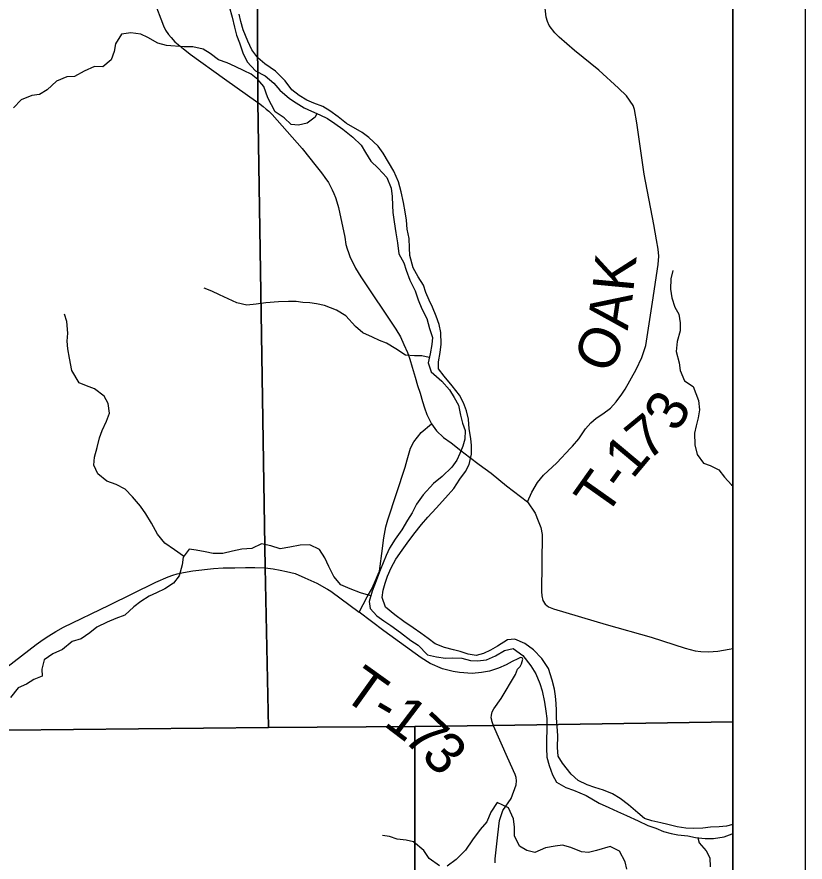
# Model space of a CAD drawing. Extents: x 0 to 34, y 0 to 22.
# Drawn here: x 7.911 to 9, y 15.737 to 16.905 of the extents above; entities that cross this region are included whole.
import ezdxf

# ---------------------------------------------------------------- set-up
doc = ezdxf.new("R2010")
doc.units = 0
for name, color, linetype in [('Default', 7, 'Continuous'), ('GM_X_County_Road', 7, 'Continuous'), ('GM_X_Minor_River', 7, 'Continuous'), ('GM_X_Township_Road', 7, 'Continuous'), ('GM_X_Township_Road_Text', 7, 'Continuous'), ('SH_Cut_Line', 7, 'Continuous'), ('SH_Data', 7, 'Continuous')]:
    doc.layers.add(name, color=color, linetype=linetype)

msp = doc.modelspace()

# ---------------------------------------------------------------- linework, layer by layer
at = {"layer": 'Default'}
for points in [[(8.9, 15.9304), (8.9, 20.9), (8.1749, 20.9), (8.1859, 20.3892), (8.1995, 19.7718), (8.2061, 19.4737), (8.2069, 19.4369), (8.2195, 18.875), (8.2216, 18.8361), (8.2229, 18.8136), (8.2232, 18.7798), (8.2237, 18.7271), (8.2254, 18.6464), (8.2283, 18.4271), (8.2338, 18.0126), (8.2361, 17.5877), (8.2392, 17.3521), (8.2417, 17.2403), (8.2434, 16.7876), (8.2536, 16.1438), (8.2582, 15.9227), (8.4608, 15.9241), (8.569, 15.9256)], [(8.4439, 14.1), (8.9, 14.1), (8.9, 15.9304), (8.569, 15.9256), (8.4608, 15.9241), (8.4608, 15.4787), (8.4328, 14.5554), (8.4328, 14.555), (8.4391, 14.4529)]]:
    msp.add_lwpolyline(points, close=True, dxfattribs=at)
for points in [[(6.5781, 15.8955), (6.9232, 15.9027), (7.0184, 15.9049), (7.3026, 15.9113), (7.5392, 15.9156), (8.2582, 15.9227), (8.2536, 16.1438), (8.2434, 16.7876), (8.2417, 17.2403), (8.2392, 17.3521), (8.2361, 17.5877), (8.2338, 18.0126), (8.2283, 18.4271), (8.2254, 18.6464), (8.2237, 18.7271), (8.2232, 18.7798), (8.2229, 18.8136), (8.2216, 18.8361), (8.2195, 18.875), (8.2069, 19.4369), (8.2061, 19.4737), (8.1995, 19.7718), (8.1859, 20.3892)], [(8.4608, 15.4787), (8.4608, 15.9241), (8.2582, 15.9227), (7.5392, 15.9156), (7.3026, 15.9113), (7.0184, 15.9049), (6.9232, 15.9027), (6.5781, 15.8955), (6.4918, 15.8937), (6.4353, 15.8916), (6.4145, 15.8911), (6.2639, 15.8885), (6.1922, 15.8873), (6.1703, 15.8865), (6.065, 15.8836), (5.9591, 15.8823), (5.7768, 15.8771), (5.0185, 15.8642), (4.6273, 15.8569), (4.3446, 15.8524)]]:
    msp.add_lwpolyline(points, dxfattribs=at)
at = {"layer": 'GM_X_County_Road'}
for points in [[(8.1, 16.9277), (8.113, 16.8928), (8.116, 16.8867), (8.12, 16.881), (8.1236, 16.8767), (8.1287, 16.8707), (8.1379, 16.8633), (8.1501, 16.8538), (8.1977, 16.8195), (8.2436, 16.787), (8.2445, 16.7863)], [(8.2445, 16.7863), (8.2512, 16.7811), (8.2552, 16.7777), (8.2586, 16.775), (8.2636, 16.7704), (8.3048, 16.7232), (8.3242, 16.6989), (8.3298, 16.6918), (8.3328, 16.6878), (8.3362, 16.6829), (8.3411, 16.6763), (8.3463, 16.6663), (8.3488, 16.6608), (8.3509, 16.6555), (8.3527, 16.6496), (8.3549, 16.6415), (8.3637, 16.6005), (8.3654, 16.5906), (8.3669, 16.5843), (8.3688, 16.5794), (8.3713, 16.5725), (8.3752, 16.5646), (8.3785, 16.5579), (8.3858, 16.5459), (8.4344, 16.4733), (8.4406, 16.4627), (8.4455, 16.4521), (8.4503, 16.4413), (8.4536, 16.4318), (8.457, 16.4208), (8.4612, 16.4072), (8.4643, 16.3954), (8.4681, 16.3849), (8.4712, 16.3736), (8.474, 16.3646), (8.4773, 16.3554), (8.4838, 16.3427)], [(8.3838, 16.0822), (8.3946, 16.1032), (8.4005, 16.1136), (8.405, 16.1227), (8.4099, 16.1346), (8.4116, 16.1387), (8.4125, 16.1456), (8.4152, 16.1633), (8.4179, 16.1851), (8.4207, 16.2), (8.4233, 16.2099), (8.4472, 16.2826), (8.4501, 16.2926), (8.4528, 16.3024), (8.4547, 16.3088), (8.4594, 16.3176), (8.4641, 16.3242), (8.4694, 16.3304), (8.4838, 16.3427)], [(8.4838, 16.3427), (8.4904, 16.3331), (8.5004, 16.3239), (8.5107, 16.3161), (8.5243, 16.3057), (8.5361, 16.2963), (8.5496, 16.2864), (8.5662, 16.2742), (8.5871, 16.2568), (8.6161, 16.2346)], [(8.6161, 16.2346), (8.6267, 16.2192), (8.6311, 16.2087), (8.6347, 16.1995), (8.6367, 16.1894), (8.6358, 16.1108), (8.636, 16.1048), (8.6377, 16.0984), (8.6406, 16.0933), (8.6455, 16.0894), (8.6522, 16.0869), (8.725, 16.0654), (8.7874, 16.0475), (8.8342, 16.0323), (8.8482, 16.0288), (8.856, 16.0277), (8.8666, 16.0272), (8.8795, 16.0283), (8.895, 16.0309), (8.9, 16.032)], [(7.8455, 15.9669), (7.9373, 16.0373), (7.9469, 16.0446), (7.9549, 16.0493), (7.9646, 16.0555), (7.9748, 16.0614), (8.0382, 16.092), (8.1027, 16.1239), (8.1197, 16.131), (8.1263, 16.1333), (8.1322, 16.1353), (8.1384, 16.1367), (8.146, 16.138), (8.1536, 16.1392), (8.1821, 16.1424), (8.1956, 16.1434), (8.212, 16.1436), (8.2267, 16.1439), (8.2393, 16.1438), (8.2538, 16.1433), (8.2648, 16.1423), (8.2743, 16.1404), (8.2834, 16.1385), (8.295, 16.1355), (8.3087, 16.1299), (8.3253, 16.1224), (8.3389, 16.1145), (8.3399, 16.114)], [(8.3399, 16.114), (8.3447, 16.1112), (8.3838, 16.0822)]]:
    msp.add_lwpolyline(points, dxfattribs=at)
at = {"layer": 'GM_X_Minor_River'}
for points in [[(8.2038, 16.9193), (8.2081, 16.9049), (8.2113, 16.8909), (8.214, 16.8799), (8.2183, 16.8693), (8.2229, 16.8557), (8.2287, 16.8429), (8.2402, 16.8308)], [(8.2438, 16.8487), (8.2354, 16.8596), (8.2296, 16.8714), (8.2234, 16.8872), (8.2203, 16.8986), (8.2179, 16.9088)], [(8.3252, 16.7716), (8.323, 16.7667), (8.3117, 16.7582), (8.2996, 16.7554), (8.2897, 16.7565), (8.2798, 16.7655), (8.2676, 16.7737), (8.2572, 16.7934), (8.2518, 16.8089), (8.2437, 16.8187), (8.2342, 16.8262), (8.2247, 16.8307), (8.2125, 16.8366), (8.2011, 16.8415), (8.1893, 16.8459), (8.1778, 16.8545), (8.1679, 16.8605), (8.1539, 16.8638), (8.1417, 16.8637), (8.1175, 16.8657), (8.1053, 16.8687), (8.0916, 16.8765), (8.0817, 16.8813), (8.068, 16.8831), (8.0552, 16.8815), (8.0469, 16.8677), (8.0448, 16.8574), (8.0407, 16.846), (8.0294, 16.836), (8.018, 16.8367), (8.0037, 16.8301), (7.9901, 16.8227), (7.9795, 16.8223), (7.9655, 16.8161), (7.9523, 16.8042), (7.9418, 16.798), (7.9312, 16.7964), (7.9165, 16.7905), (7.9059, 16.7794)], [(8.6864, 15.8496), (8.6769, 15.8582), (8.6646, 15.8733), (8.6588, 15.8831), (8.6576, 15.8953), (8.6582, 15.9112), (8.6574, 15.9245), (8.6565, 15.9363), (8.6564, 15.9465), (8.6559, 15.956), (8.6551, 15.9659), (8.6535, 15.9757), (8.6504, 15.9882), (8.6453, 16.0045), (8.6361, 16.0181), (8.6246, 16.0301), (8.6128, 16.0391), (8.5987, 16.0447), (8.5889, 16.0442), (8.5749, 16.0354), (8.5651, 16.0296), (8.5553, 16.0253), (8.5454, 16.0225), (8.5344, 16.024), (8.5234, 16.028), (8.5139, 16.0302), (8.5014, 16.0335), (8.4885, 16.0383), (8.4789, 16.0458), (8.469, 16.0533), (8.4583, 16.0605), (8.4454, 16.0691), (8.4328, 16.0784), (8.4202, 16.0893), (8.4155, 16.1026), (8.4169, 16.1125), (8.4195, 16.1224), (8.4228, 16.1319), (8.4277, 16.1433), (8.4344, 16.1555), (8.443, 16.1678), (8.4501, 16.1777), (8.4591, 16.19), (8.4696, 16.2033), (8.4786, 16.2137), (8.4899, 16.2259), (8.503, 16.2401), (8.5143, 16.2531), (8.5229, 16.2661), (8.5304, 16.2765), (8.5356, 16.2864), (8.5389, 16.3005), (8.5388, 16.3126), (8.5379, 16.3221), (8.5356, 16.3357), (8.5347, 16.349), (8.5319, 16.3604), (8.528, 16.3714), (8.5223, 16.382), (8.5123, 16.3952), (8.5012, 16.4083), (8.4931, 16.4185), (8.4931, 16.4284), (8.4956, 16.4413), (8.497, 16.4527), (8.4965, 16.4687), (8.4941, 16.48), (8.4899, 16.4914), (8.4852, 16.5039), (8.4802, 16.5137), (8.4759, 16.5243), (8.4728, 16.5341), (8.4651, 16.5458), (8.4582, 16.5583), (8.4539, 16.5754), (8.4531, 16.586), (8.4526, 16.5989), (8.4502, 16.6118), (8.4489, 16.6243), (8.4473, 16.6357), (8.4449, 16.6486), (8.4418, 16.6634), (8.4382, 16.677), (8.4317, 16.6917), (8.4244, 16.7042), (8.4167, 16.7167), (8.4098, 16.7265), (8.3972, 16.7385), (8.3876, 16.7452), (8.3663, 16.758), (8.3545, 16.767), (8.343, 16.7752), (8.3335, 16.7812), (8.3209, 16.786), (8.3111, 16.7901), (8.3008, 16.7965), (8.2908, 16.8043), (8.2813, 16.8168), (8.2679, 16.8303), (8.2534, 16.8401), (8.2438, 16.8487)], [(8.2402, 16.8308), (8.2539, 16.8237), (8.2657, 16.8136), (8.2738, 16.8038), (8.2872, 16.7925), (8.2967, 16.7862), (8.3077, 16.7794), (8.3176, 16.775), (8.3294, 16.7698), (8.3397, 16.7645), (8.35, 16.7578), (8.3611, 16.7499), (8.3748, 16.739), (8.3866, 16.7278), (8.3924, 16.7179), (8.3997, 16.7055), (8.41, 16.6961), (8.4219, 16.6829), (8.4281, 16.6685), (8.4293, 16.6568), (8.4298, 16.6442), (8.4303, 16.6348), (8.4319, 16.6219), (8.4343, 16.6067), (8.4367, 16.5927), (8.4387, 16.5775), (8.4453, 16.565), (8.4484, 16.5548), (8.4538, 16.5412), (8.4611, 16.5264), (8.465, 16.5139), (8.4705, 16.5015), (8.477, 16.4882), (8.4809, 16.4742), (8.4848, 16.4621), (8.4841, 16.4522), (8.4816, 16.4393), (8.4791, 16.4267), (8.4833, 16.4146), (8.4978, 16.4015), (8.5086, 16.3894), (8.5151, 16.3788), (8.5209, 16.3683), (8.5236, 16.3546), (8.5264, 16.3436), (8.5303, 16.3334), (8.5296, 16.3213), (8.527, 16.3117), (8.523, 16.3018), (8.5185, 16.2923), (8.5118, 16.2827), (8.4982, 16.2697), (8.4862, 16.2601), (8.4719, 16.2444), (8.4629, 16.2314), (8.457, 16.2196), (8.4506, 16.2096), (8.4424, 16.1959), (8.4334, 16.1833), (8.4255, 16.1706), (8.4211, 16.1604), (8.417, 16.1504), (8.4129, 16.1401), (8.407, 16.1257), (8.4018, 16.1112), (8.3974, 16.0971), (8.399, 16.0872), (8.4081, 16.0771), (8.4177, 16.0703), (8.4276, 16.0636), (8.4409, 16.0542), (8.4551, 16.043), (8.4653, 16.0366), (8.478, 16.0234), (8.4905, 16.0205), (8.503, 16.0187), (8.5133, 16.0192), (8.5254, 16.0186), (8.5375, 16.0156), (8.5474, 16.015), (8.5595, 16.0162), (8.572, 16.0217), (8.5844, 16.0294), (8.5965, 16.0318), (8.6099, 16.0224), (8.621, 16.0081), (8.6279, 15.9968), (8.6333, 15.9835), (8.6368, 15.9737), (8.64, 15.9578), (8.6416, 15.9452), (8.6429, 15.9354), (8.643, 15.9191), (8.6427, 15.9065), (8.6424, 15.8944), (8.6429, 15.8818), (8.6464, 15.8701), (8.6511, 15.8572), (8.6565, 15.8474), (8.6695, 15.8399), (8.6801, 15.8362)], [(8.8174, 16.5546), (8.8145, 16.5431), (8.8139, 16.5287), (8.8156, 16.5166), (8.8199, 16.5041), (8.8253, 16.4943), (8.8274, 16.4822), (8.8272, 16.4711), (8.8232, 16.4563), (8.8218, 16.4426), (8.8258, 16.4267), (8.8275, 16.4165), (8.8334, 16.4021), (8.8452, 16.3943), (8.8527, 16.375), (8.854, 16.3621), (8.8522, 16.3511), (8.8493, 16.3396), (8.8472, 16.3297), (8.8474, 16.3134), (8.851, 16.3002), (8.8595, 16.2881), (8.869, 16.2852), (8.8808, 16.2789), (8.8885, 16.2688), (8.8985, 16.2583), (8.9, 16.2568)], [(8.4806, 16.4343), (8.4703, 16.4365), (8.46, 16.4368), (8.4475, 16.4374), (8.4345, 16.4464), (8.4216, 16.4539), (8.4117, 16.458), (8.4022, 16.4625), (8.3885, 16.4684), (8.3786, 16.477), (8.3652, 16.4917), (8.3522, 16.4996), (8.3358, 16.5063), (8.3248, 16.5084), (8.3153, 16.5099), (8.3059, 16.5105), (8.2964, 16.5116), (8.2858, 16.5119), (8.2721, 16.5114), (8.2547, 16.5097), (8.2415, 16.508), (8.2282, 16.5068), (8.2145, 16.5097), (8.2027, 16.5153), (8.1905, 16.5208), (8.1799, 16.526), (8.1696, 16.5301)], [(8.141, 16.1595), (8.1284, 16.1686), (8.115, 16.1776), (8.1047, 16.19), (8.0966, 16.2051), (8.0889, 16.2183), (8.0812, 16.2289), (8.0705, 16.2417), (8.0602, 16.2522), (8.048, 16.2586), (8.0351, 16.2634), (8.0225, 16.2735), (8.0171, 16.2856), (8.0177, 16.2963), (8.0214, 16.31), (8.0247, 16.3233), (8.0284, 16.3336), (8.0344, 16.3462), (8.0384, 16.3572), (8.0368, 16.3709), (8.0314, 16.3807), (8.0177, 16.3908), (8.0066, 16.3953), (7.9968, 16.3994), (7.9864, 16.4164), (7.9832, 16.4334), (7.9808, 16.4463), (7.98, 16.4569), (7.981, 16.468), (7.9797, 16.4839), (7.9766, 16.4941)], [(8.3997, 16.1047), (8.3855, 16.1091), (8.3711, 16.1143), (8.3585, 16.1199), (8.3485, 16.1316), (8.3416, 16.1452), (8.3362, 16.1573), (8.3289, 16.169), (8.3156, 16.1753), (8.3019, 16.1748), (8.2879, 16.172), (8.2743, 16.17), (8.2617, 16.174), (8.2488, 16.1769), (8.2352, 16.1704), (8.2216, 16.1695), (8.2084, 16.1667), (8.1951, 16.1631), (8.1819, 16.1634), (8.1709, 16.1656), (8.1583, 16.1681), (8.1488, 16.1692), (8.1402, 16.1584), (8.1392, 16.1478), (8.1347, 16.1326), (8.1269, 16.1222), (8.1152, 16.1145), (8.1035, 16.1091), (8.0933, 16.1045), (8.082, 16.0971), (8.0722, 16.0898), (8.0598, 16.0783), (8.0473, 16.0733), (8.0352, 16.0682), (8.0213, 16.0616), (8.0115, 16.0535), (7.9994, 16.0455), (7.9869, 16.0415), (7.9738, 16.0308), (7.9602, 16.0246), (7.9485, 16.0165), (7.9452, 16.0035), (7.9453, 15.9937), (7.9339, 15.989), (7.9238, 15.9828), (7.9124, 15.9774), (7.9019, 15.9644)], [(8.9, 15.7886), (8.8913, 15.7866), (8.8811, 15.7854), (8.8693, 15.7849), (8.8587, 15.7836), (8.8454, 15.7831), (8.8352, 15.7838), (8.8234, 15.7856), (8.8101, 15.7889), (8.8006, 15.7911), (8.7881, 15.7936), (8.7782, 15.7969), (8.7687, 15.8048), (8.7557, 15.8161), (8.7446, 15.8247), (8.7336, 15.8311), (8.7214, 15.8363), (8.7096, 15.8399), (8.699, 15.8433), (8.6864, 15.8496)], [(8.6801, 15.8362), (8.6972, 15.8288), (8.7155, 15.8184), (8.7288, 15.8124), (8.7406, 15.8068), (8.7532, 15.8012), (8.7692, 15.7938), (8.7825, 15.7875), (8.7935, 15.7834), (8.8045, 15.7789), (8.8148, 15.7764), (8.8243, 15.7746), (8.8379, 15.7728), (8.8486, 15.7706), (8.8619, 15.7692), (8.8736, 15.7694), (8.888, 15.7718), (8.899, 15.776), (8.9, 15.7763)], [(8.7534, 15.7268), (8.7515, 15.7371), (8.7437, 15.7518), (8.7304, 15.7581), (8.7119, 15.7526), (8.7005, 15.7499), (8.6911, 15.7509), (8.6762, 15.7568), (8.6645, 15.7601), (8.6546, 15.7589), (8.6414, 15.7565), (8.6266, 15.7499), (8.6156, 15.7528), (8.6053, 15.7588), (8.5984, 15.7732), (8.5983, 15.785), (8.597, 15.7963), (8.5901, 15.8118), (8.5745, 15.8193), (8.5655, 15.8059), (8.5599, 15.7926), (8.5509, 15.7818), (8.5404, 15.7673), (8.5307, 15.7532), (8.5179, 15.7401), (8.5051, 15.7313)], [(8.4949, 15.7316), (8.4804, 15.7417), (8.4731, 15.7526), (8.4586, 15.7646), (8.4487, 15.7668), (8.4362, 15.7682), (8.4255, 15.7723), (8.4157, 15.7733)], [(8.8518, 15.7703), (8.8536, 15.7635), (8.8631, 15.7525), (8.8682, 15.7427), (8.869, 15.7302)]]:
    msp.add_lwpolyline(points, dxfattribs=at)
at = {"layer": 'GM_X_Township_Road'}
for points in [[(8.7465, 16.3836), (8.7512, 16.3903), (8.7666, 16.4179), (8.7743, 16.4344), (8.78, 16.4508), (8.7889, 16.5106), (8.7971, 16.5628), (8.7978, 16.5745), (8.7971, 16.5842), (8.7948, 16.597), (8.7908, 16.6183), (8.7775, 16.6876), (8.7674, 16.7587), (8.7642, 16.7772), (8.7626, 16.7826), (8.753, 16.7962), (8.7423, 16.8067), (8.7147, 16.8314), (8.6812, 16.8586), (8.66, 16.877), (8.6543, 16.8832), (8.6464, 16.8933), (8.6439, 16.8987), (8.6421, 16.9049), (8.6406, 16.917)], [(8.6785, 16.3119), (8.6872, 16.3218), (8.6963, 16.3357), (8.7037, 16.3441), (8.7114, 16.3505), (8.7203, 16.3562), (8.7312, 16.3644), (8.7389, 16.3728), (8.7465, 16.3836)], [(8.3838, 16.0822), (8.3946, 16.1032), (8.4005, 16.1136), (8.405, 16.1227), (8.4099, 16.1346), (8.4116, 16.1387), (8.4125, 16.1456), (8.4152, 16.1633), (8.4179, 16.1851), (8.4207, 16.2), (8.4233, 16.2099), (8.4472, 16.2826), (8.4501, 16.2926), (8.4528, 16.3024), (8.4547, 16.3088), (8.4594, 16.3176), (8.4641, 16.3242), (8.4694, 16.3304), (8.4838, 16.3427)], [(8.4838, 16.3427), (8.4904, 16.3331), (8.5004, 16.3239), (8.5107, 16.3161), (8.5243, 16.3057), (8.5361, 16.2963), (8.5496, 16.2864), (8.5662, 16.2742), (8.5871, 16.2568), (8.6161, 16.2346)], [(8.6161, 16.2346), (8.6225, 16.2479), (8.6301, 16.2616), (8.6385, 16.2714), (8.6567, 16.2887), (8.6758, 16.3089), (8.6785, 16.3119)], [(8.5668, 15.9329), (8.5661, 15.9362), (8.5665, 15.94), (8.5675, 15.9446), (8.57, 15.9487), (8.5797, 15.9631), (8.5996, 15.9959), (8.6025, 16.0036), (8.6061, 16.0073), (8.6079, 16.011), (8.6089, 16.014), (8.6097, 16.0171), (8.6091, 16.0193), (8.6065, 16.0197), (8.603, 16.0179), (8.5953, 16.014), (8.5869, 16.0094), (8.5763, 16.0049), (8.5639, 16.0008), (8.5527, 15.9986), (8.54, 15.9973), (8.5225, 15.999), (8.5135, 16.0004), (8.4987, 16.0039), (8.4818, 16.0113), (8.4694, 16.019), (8.4176, 16.0564), (8.3838, 16.0822)], [(8.5718, 15.7355), (8.5716, 15.7414), (8.5753, 15.7746), (8.5776, 15.7941), (8.5821, 15.8082), (8.5937, 15.8245), (8.6008, 15.8437), (8.6011, 15.849), (8.6008, 15.8535), (8.5993, 15.8578), (8.5889, 15.8812), (8.5692, 15.925), (8.5669, 15.9321), (8.5668, 15.9329)]]:
    msp.add_lwpolyline(points, dxfattribs=at)
msp.add_lwpolyline([(8.4439, 14.1), (8.9, 14.1), (8.9, 15.9304), (8.569, 15.9256), (8.4608, 15.9241), (8.4608, 15.4787), (8.4328, 14.5552), (8.4328, 14.555), (8.4391, 14.4529)], close=True, dxfattribs=at)
at = {"layer": 'SH_Cut_Line'}
msp.add_lwpolyline([(3.2807, 14.1), (8.9, 14.1), (8.9, 20.9), (3.2826, 20.9), (3.2843, 20.6124), (3.2845, 20.5998), (3.2888, 19.8918), (3.2901, 19.68), (3.2904, 19.1173), (3.2907, 18.4315), (3.2837, 17.3796), (3.2835, 17.0107), (3.2832, 16.3898), (3.2829, 15.8433), (3.2815, 15.7537), (3.2811, 15.7294), (3.2832, 14.8896), (3.2841, 14.501), (3.2822, 14.2781), (3.2808, 14.1155)], close=True, dxfattribs=at)
at = {"layer": 'SH_Data'}
for p, q in [((9, 21), (9, 14)), ((8.9, 20.9), (8.9, 14.1))]:
    msp.add_line(p, q, dxfattribs=at)

# ---------------------------------------------------------------- texts
at = {"layer": 'GM_X_Township_Road_Text'}
for s, rotation, p in [('K', 84.5879, (8.7625, 16.5238)), ('A', 81.5867, (8.7548, 16.4711)), ('O', 66.2886, (8.7301, 16.4094)), ('3', 60.1765, (8.8233, 16.3291)), ('7', 39.5124, (8.7819, 16.2899)), ('1', 50.0478, (8.7614, 16.265)), ('T', 54.7254, (8.7239, 16.2124)), ('-', 54.0231, (8.7484, 16.2469)), ('T', 324.4245, (8.3579, 15.9652)), ('-', 329.5705, (8.3971, 15.9374)), ('1', 322.7585, (8.4157, 15.9266)), ('7', 316.4058, (8.4423, 15.9065)), ('3', 315.3901, (8.4675, 15.8825))]:
    msp.add_text(s, height=0.0568, rotation=rotation, dxfattribs=at).set_placement(p)

doc.saveas('drawing.dxf')
